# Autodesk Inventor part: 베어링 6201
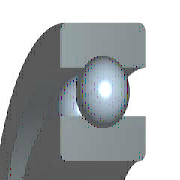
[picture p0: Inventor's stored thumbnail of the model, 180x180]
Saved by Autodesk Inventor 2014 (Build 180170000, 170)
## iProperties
Created: 2015-12
Part Number: 베어링 6201
Material: 강철, 연강
Description: 깊은 그루브 볼 베어링
Document SubType Name: Modeling
Standard: KS B 2023
Designer: mdu
Standards Organization: KS
Language: ko-KR
Size Designation: 6201 - 12 x 32 x 10
Categories: <MemberInstance><Categories><Category DisplayName="샤프트 부품" InternalName="7f7aeb1f-a693-4053-b835-cee3144e0d98" Mnemonic="SHFT"><Category DisplayName="베어링" Inter
Density: 7.86 g/cm^3
Mass: 36.8026 g
Surface Area: 42.5728 cm^2
Volume: 4.68226 cm^3
Appearance: 진녹색
Company: 한국ATC센터
IsCustomPart: 1
Author: mdu
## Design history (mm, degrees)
sketch "스케치" dims "d0" = 5.2 (= -0.26 x WD + 0.26 x BD)
  geometry: L1 (2.4, 11)-(7.6, 11); L2 (5, 11)-(5, 8.4); L3 (5, 11)-(5, 13.6); L4 (3.068, 9.26)-(0, 9.26); L5 (0, 6)-(10, 6); L6 (3.068, 12.74)-(0, 12.74); L7 (0, 16)-(10, 16); L8 (10, 6)-(10, 9.26); L9 (6.932, 9.26)-(10, 9.26); L10 (6.932, 12.74)-(10, 12.74); L11 (10, 16)-(10, 12.74); L12 (-1.4, 0)-(8.4, 0) reference; L13 (0, -0.3)-(0, 5.3) reference
  constraints: 22 end point, 4 point on line, 2 collinear, 2 perpendicular, 2 symmetric about line, 1 midpoint, 1 parallel, 14 other
  dimensions: "d9" = 12 diameter of L5 L12 (= WD); "d11" = 32 diameter of L7 L12 (= BD); "d12" = 10 distance between parallel lines of L8 L13 (= KB); "d13" = 18.52 diameter of L9 L12 (= 0.326 x BD + 0.674 x WD)
revolve "본체" stored, may be unused: angle "d6" = 90 deg
revolve "볼" stored, may be unused: angle "d7" = 90 deg
pattern_circular "IDS_ARRAYBALL[SIMPL:T]" dims angle "d3" = 360 deg
body "Solid1"
fillet "모깎기1" dims "d1" = 0.6 (= KRS)
other parameters: "WD" = 12 [user parameter; used in 5 equation terms], "BD" = 32 [user parameter; used in 5 equation terms], "KB" = 10 [user parameter; used in 1 equation term], "KRS" = 0.6 [user parameter; used in 1 equation term], "d4" = 0, "d5" = 0, "d8" = 0, "d14" = 0, "d15" = 0, "BBA" = 0 [user parameter], "BC0" = 3100000 [user parameter], "BC" = 6890000 [user parameter], "BR" = 16 (= 0.5 x BD) [user parameter], "WR" = 6 (= 0.5 x WD) [user parameter]
